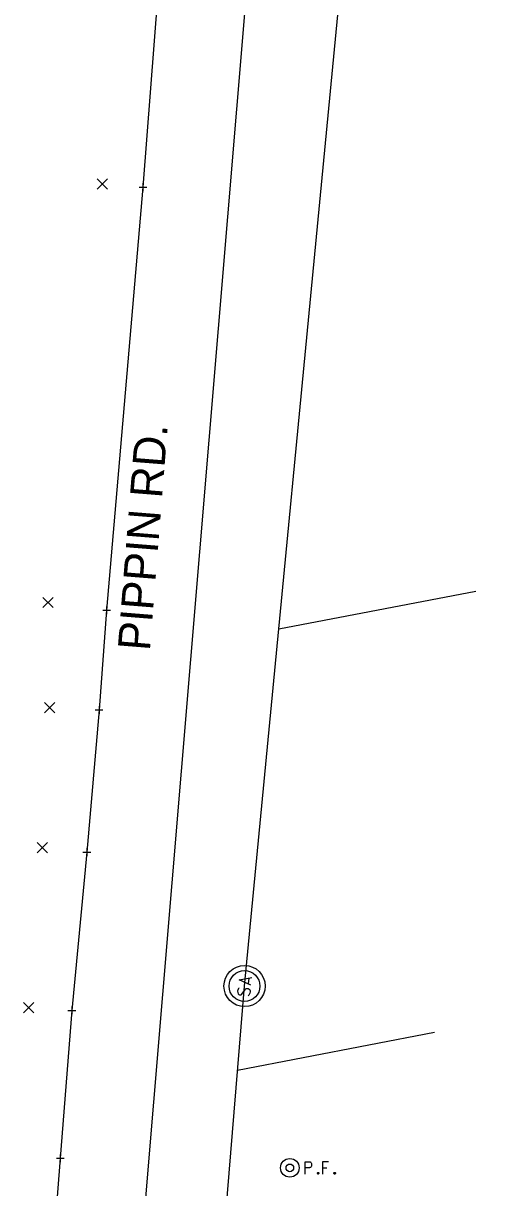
# Model space of a CAD drawing. Extents: x 1380440 to 1381945, y 468756 to 470369.
# Drawn here: x 1381570.5 to 1381630.3, y 469686 to 469836.8 of the extents above; entities that cross this region are included whole.
import ezdxf

# ---------------------------------------------------------------- set-up
doc = ezdxf.new("R2010")
doc.units = 0
for name, color, linetype in [('GE_P_Driveway_CL', 7, 'Continuous'), ('PM_X_CL_Double_Solid', 7, 'Continuous'), ('PV_P_Curb_Ramp', 7, 'Continuous'), ('PV_P_EOP', 7, 'Continuous'), ('SC_Scratch1', 7, 'Continuous'), ('SC_Shading1', 7, 'Continuous'), ('SH_Named_Boundary', 7, 'Continuous'), ('UT_X_Sanitary_Line', 7, 'Continuous'), ('UT_X_Water', 7, 'Continuous'), ('X-SUBDIVISION', 7, 'Continuous')]:
    doc.layers.add(name, color=color, linetype=linetype)

msp = doc.modelspace()

# ---------------------------------------------------------------- linework, layer by layer
at = {"layer": 'GE_P_Driveway_CL'}
for p, q in [((1381580.06, 469815.31), (1381581.4, 469816.64)), ((1381580.06, 469816.64), (1381581.4, 469815.31)), ((1381573.03, 469761.11), (1381574.37, 469762.44)), ((1381573.03, 469762.44), (1381574.37, 469761.11)), ((1381573.23, 469747.47), (1381574.57, 469748.81)), ((1381573.23, 469748.81), (1381574.57, 469747.47)), ((1381572.27, 469729.36), (1381573.61, 469730.69)), ((1381572.27, 469730.69), (1381573.61, 469729.36)), ((1381570.51, 469708.63), (1381571.85, 469709.97)), ((1381570.51, 469709.97), (1381571.85, 469708.63))]:
    msp.add_line(p, q, dxfattribs=at)
at = {"layer": 'PM_X_CL_Double_Solid'}
msp.add_lwpolyline([(1381618.76, 470220.14), (1381616.92, 470200.19), (1381615.1, 470178.83), (1381610.95, 470124.78), (1381606.49, 470071.23), (1381602.26, 470019.36), (1381598.18, 469969.8), (1381595.01, 469928.06), (1381590.91, 469878.81), (1381589.36, 469859.11), (1381585.99, 469815.58), (1381581.29, 469760.78), (1381580.3, 469747.86), (1381578.72, 469729.45), (1381576.78, 469708.95), (1381575.29, 469689.79), (1381572.76, 469657.56), (1381569.36, 469615.7), (1381565.36, 469567.23), (1381561.16, 469537.52), (1381558.94, 469486.81), (1381555.39, 469442.03), (1381550.97, 469391.02)], dxfattribs=at)
at = {"layer": 'PV_P_Curb_Ramp'}
for p, q in [((1381597.17, 469712.35), (1381597.17, 469712.35)), ((1381599.15, 469712.1), (1381599.15, 469712.1)), ((1381599.15, 469712.1), (1381599.15, 469712.1)), ((1381599.15, 469712.1), (1381599.15, 469712.1)), ((1381601.14, 469711.85), (1381601.14, 469711.85))]:
    msp.add_line(p, q, dxfattribs=at)
msp.add_circle((1381599.15, 469712.1), 2, dxfattribs=at)
at = {"layer": 'PV_P_EOP'}
for points in [[(1381599.97, 469712.21), (1381598.45, 469712.91), (1381600.1, 469713.2)], [(1381598.43, 469711.86), (1381598.4, 469711.84), (1381598.37, 469711.8), (1381598.32, 469711.7), (1381598.28, 469711.56), (1381598.26, 469711.46), (1381598.26, 469711.42), (1381598.28, 469711.26), (1381598.33, 469711.11), (1381598.42, 469711.01), (1381598.52, 469710.97), (1381598.59, 469710.96), (1381598.7, 469710.98), (1381598.8, 469711.06), (1381599.26, 469711.7), (1381599.32, 469711.76), (1381599.37, 469711.78), (1381599.45, 469711.79), (1381599.52, 469711.78), (1381599.6, 469711.76), (1381599.65, 469711.74), (1381599.71, 469711.71), (1381599.75, 469711.68), (1381599.79, 469711.65), (1381599.82, 469711.61), (1381599.84, 469711.57), (1381599.86, 469711.51), (1381599.87, 469711.48), (1381599.86, 469711.36), (1381599.84, 469711.19), (1381599.8, 469711.08), (1381599.69, 469710.93), (1381599.61, 469710.83)], [(1381599.71, 469713.12), (1381599.61, 469712.38)]]:
    msp.add_lwpolyline(points, dxfattribs=at)
for radius in [2.67, 2]:
    msp.add_circle((1381599.15, 469712.1), radius, dxfattribs=at)
at = {"layer": 'SC_Scratch1'}
for points in [[(1381607.02, 469687.75), (1381607.02, 469689.35), (1381607.55, 469689.35), (1381607.6, 469689.34), (1381607.68, 469689.31), (1381607.71, 469689.28), (1381607.74, 469689.26), (1381607.79, 469689.2), (1381607.82, 469689.13), (1381607.84, 469689.03), (1381607.84, 469688.88), (1381607.83, 469688.83), (1381607.81, 469688.76), (1381607.77, 469688.67), (1381607.72, 469688.63), (1381607.69, 469688.6), (1381607.63, 469688.58), (1381607.55, 469688.57), (1381607.02, 469688.57)], [(1381610.03, 469689.35), (1381609.27, 469689.35), (1381609.27, 469687.75)], [(1381608.66, 469687.96), (1381608.71, 469687.96), (1381608.75, 469687.94), (1381608.78, 469687.89), (1381608.78, 469687.82), (1381608.75, 469687.77), (1381608.71, 469687.75), (1381608.66, 469687.75), (1381608.63, 469687.77), (1381608.59, 469687.82), (1381608.59, 469687.89), (1381608.63, 469687.94), (1381608.66, 469687.96)], [(1381609.27, 469688.57), (1381609.81, 469688.57)], [(1381610.81, 469687.96), (1381610.86, 469687.96), (1381610.9, 469687.94), (1381610.93, 469687.89), (1381610.93, 469687.82), (1381610.9, 469687.77), (1381610.86, 469687.75), (1381610.81, 469687.75), (1381610.78, 469687.77), (1381610.74, 469687.82), (1381610.74, 469687.89), (1381610.78, 469687.94), (1381610.81, 469687.96)]]:
    msp.add_lwpolyline(points, dxfattribs=at)
for radius in [1.2, 0.495]:
    msp.add_circle((1381605.02, 469688.55), radius, dxfattribs=at)
at = {"layer": 'SC_Shading1'}
msp.add_lwpolyline([(1381589.36, 469859.11), (1381585.99, 469815.58), (1381581.29, 469760.78), (1381580.3, 469747.86), (1381578.72, 469729.45), (1381576.78, 469708.95), (1381575.29, 469689.79), (1381572.76, 469657.56), (1381569.36, 469615.7), (1381565.36, 469567.23), (1381561.16, 469537.52), (1381558.94, 469486.81), (1381555.39, 469442.03), (1381550.97, 469391.02)], dxfattribs=at)
at = {"layer": 'SH_Named_Boundary'}
for p, q in [((1381585.99, 469816.08), (1381585.99, 469815.08)), ((1381585.49, 469815.58), (1381586.49, 469815.58)), ((1381585.99, 469815.58), (1381585.99, 469815.58)), ((1381580.79, 469760.78), (1381581.79, 469760.78)), ((1381581.29, 469761.28), (1381581.29, 469760.28)), ((1381581.29, 469760.78), (1381581.29, 469760.78)), ((1381579.8, 469747.86), (1381580.8, 469747.86)), ((1381580.3, 469748.36), (1381580.3, 469747.36)), ((1381580.3, 469747.86), (1381580.3, 469747.86)), ((1381578.72, 469729.95), (1381578.72, 469728.95)), ((1381578.22, 469729.45), (1381579.22, 469729.45)), ((1381578.72, 469729.45), (1381578.72, 469729.45)), ((1381576.28, 469708.95), (1381577.28, 469708.95)), ((1381576.78, 469709.45), (1381576.78, 469708.45)), ((1381576.78, 469708.95), (1381576.78, 469708.95)), ((1381574.79, 469689.79), (1381575.79, 469689.79)), ((1381575.29, 469690.29), (1381575.29, 469689.29)), ((1381575.29, 469689.79), (1381575.29, 469689.79))]:
    msp.add_line(p, q, dxfattribs=at)
at = {"layer": 'UT_X_Sanitary_Line'}
for p, q in [((1381599.15, 469712.1), (1381615.04, 469877.56)), ((1381629.11, 469763.22), (1381603.59, 469758.34)), ((1381576.01, 469430.09), (1381599.15, 469712.1)), ((1381623.77, 469706.06), (1381598.26, 469701.18))]:
    msp.add_line(p, q, dxfattribs=at)
at = {"layer": 'UT_X_Water'}
msp.add_line((1381545.41, 469194.71), (1381630.26, 470209.69), dxfattribs=at)

# ---------------------------------------------------------------- texts
at = {"layer": 'X-SUBDIVISION'}
msp.add_text('PIPPIN RD.', height=4.167, rotation=85.4428, dxfattribs=at).set_placement((1381586.88, 469755.44))

doc.saveas('drawing.dxf')
